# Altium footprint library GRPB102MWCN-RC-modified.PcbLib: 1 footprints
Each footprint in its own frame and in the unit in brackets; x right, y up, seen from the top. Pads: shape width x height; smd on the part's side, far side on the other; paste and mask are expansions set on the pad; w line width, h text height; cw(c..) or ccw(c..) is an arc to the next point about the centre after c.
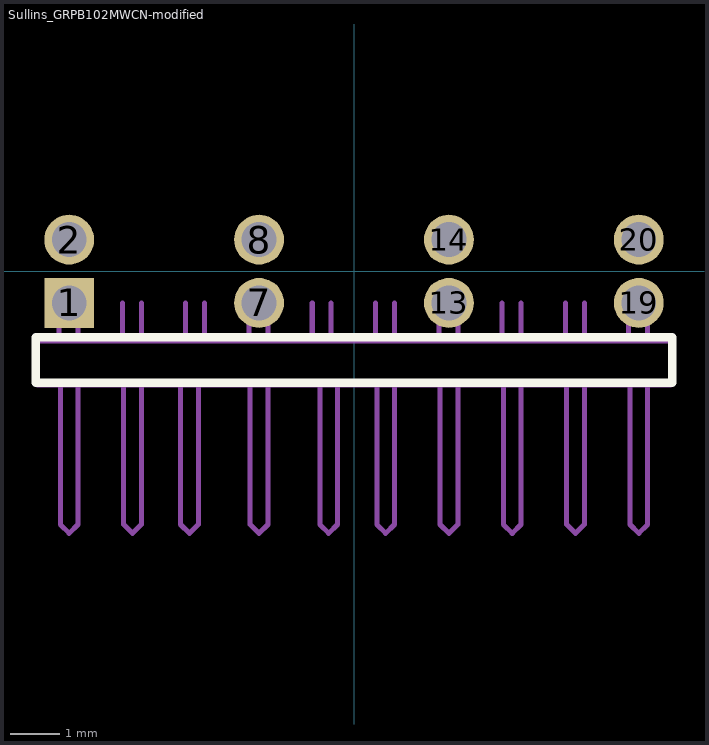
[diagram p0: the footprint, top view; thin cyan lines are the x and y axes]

## Sullins_GRPB102MWCN-modified [mm] "SULLINS"
height 3.4
pads (8):
  rect 1x1 hole 0.7: 1(-5.715,-0.635)
  round 1 hole 0.7: 2(-5.715,0.635) 7(-1.905,-0.635) 8(-1.905,0.635) 13(1.905,-0.635) 14(1.905,0.635) 19(5.715,-0.635) 20(5.715,0.635)
Top Overlay:
  lines w0.17: -6.385,-2.233 6.135,-2.233 6.385,-2.233 6.385,-1.323 -6.385,-1.323 -6.385,-2.233
M5 Assembly Top:
  lines w0.1: -6.355,-2.285 6.355,-2.285 6.355,-1.4 -6.355,-1.4 -6.355,-2.285
  lines w0.102: -5.918,-1.4 -5.918,-0.635 ; -5.893,-2.285 -5.893,-5.08 -5.715,-5.258 -5.537,-5.08 -5.537,-2.286 ; -5.537,-1.397 -5.537,-0.635 ; -4.648,-1.4 -4.648,-0.635 ; -4.623,-2.285 -4.623,-5.08 -4.445,-5.258 -4.267,-5.08 -4.267,-2.286 ; -4.267,-1.397 -4.267,-0.635 ; -3.48,-2.285 -3.48,-5.08 -3.302,-5.258 -3.124,-5.08 -3.124,-2.286 ; -3.378,-1.4 -3.378,-0.635 ; -2.997,-1.397 -2.997,-0.635 ; -2.108,-1.4 -2.108,-0.635 ; -2.083,-2.285 -2.083,-5.08 -1.905,-5.258 -1.727,-5.08 -1.727,-2.286 ; -1.727,-1.397 -1.727,-0.635 ; -0.838,-1.4 -0.838,-0.635 ; -0.686,-2.285 -0.686,-5.08 -0.508,-5.258 -0.33,-5.08 -0.33,-2.286 ; -0.457,-1.397 -0.457,-0.635 ; 0.432,-1.4 0.432,-0.635 ; 0.457,-2.285 0.457,-5.08 0.635,-5.258 0.813,-5.08 0.813,-2.286 ; 0.813,-1.397 0.813,-0.635 ; 1.702,-1.4 1.702,-0.635 ; 1.727,-2.285 1.727,-5.08 1.905,-5.258 2.083,-5.08 2.083,-2.286 ; 2.083,-1.397 2.083,-0.635 ; 2.972,-1.4 2.972,-0.635 ; 2.997,-2.285 2.997,-5.08 3.175,-5.258 3.353,-5.08 3.353,-2.286 ; 3.353,-1.397 3.353,-0.635 ; 4.242,-1.4 4.242,-0.635 ; 4.267,-2.285 4.267,-5.08 4.445,-5.258 4.623,-5.08 4.623,-2.286 ; 4.623,-1.397 4.623,-0.635 ; 5.512,-1.4 5.512,-0.635 ; 5.537,-2.285 5.537,-5.08 5.715,-5.258 5.893,-5.08 5.893,-2.286 ; 5.893,-1.397 5.893,-0.635
  text ".Designator" at -1.905,-0.127 h1.02
3D body "Sullins_GRPB102MWCN-RC.stp": height 3.41, standoff -2.49, extent -6.35,-5.285 6.35,0.835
